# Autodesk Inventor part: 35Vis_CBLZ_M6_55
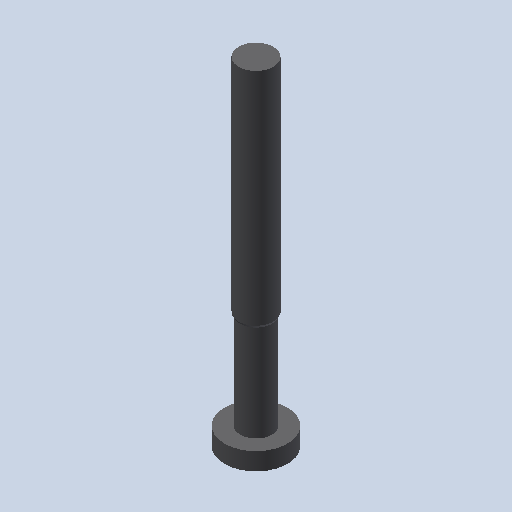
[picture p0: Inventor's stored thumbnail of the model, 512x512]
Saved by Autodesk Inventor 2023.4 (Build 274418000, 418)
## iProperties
Created: 2011-01
Part Number: 35Vis_CBLZ_M6_55
Document SubType Name: Modeling
Designer: eric
Density: 1 g/cm^3
Mass: 1.76846 g
Surface Area: 13.588 cm^2
Volume: 1.76846 cm^3
Material: Générique
Appearance: Red
Author: eric
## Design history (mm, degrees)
feature "Base1"
node "Corps solides"
node "Corps surfaciques"
node "Solide1"
